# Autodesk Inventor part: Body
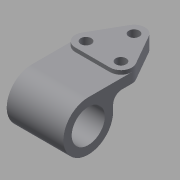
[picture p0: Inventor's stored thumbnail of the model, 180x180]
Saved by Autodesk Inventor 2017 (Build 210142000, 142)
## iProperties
Created: 2010-03
Part Number: Body
Document SubType Name: Modeling
Designer: bhakira
Density: 1 g/cm^3
Material: Generic
Appearance: Default
Author: bhakira
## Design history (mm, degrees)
sketch "Sketch1"
  geometry: L1 (10.853, 41.202)-(30.853, 6.202); L2 (-10.853, 41.202)-(-30.853, 6.202); L3 (-20, -12.5)-(20, -12.5); C1 r 6 at (0, 35); A1 r 12.5 centre (0, 35) between (10.853, 41.202) and (-10.853, 41.202); A2 r 12.5 centre (-20, 0) between (-30.853, 6.202) and (-20, -12.5); A3 r 12.5 centre (20, 0) between (20, -12.5) and (30.853, 6.202); 1 further point
  constraints: 6 end point, 6 point on circle, 6 tangent, 4 centre point, 3 horizontal alignment, 2 equal radius, 1 coincident, 1 vertical alignment, 1 other
  dimensions: "d25" = 35 vertical distance of A1.centre A2.centre; "d27" = 12.5 radius of A1; "d28" = 40 distance of A3.centre A2.centre; "d29" = 20 horizontal distance of A3.centre A1.centre
extrude "Extrusion1" new body sketch "Sketch1" distance "d6" = 16; taper "d7" = 0 deg
workplane "Work Plane2"
workplane "Work Plane3"
sketch "Sketch2"
  geometry: L1 (0, 11.5)-(0, 0); L2 (-12.5, 16)-(6.202, 16) reference; L3 (-50, 11.5)-(0, 11.5); L4 (0, 0)-(-21.5, 0); L5 (-21.5, -17)-(-21.5, 0); L6 (-12.5, 0)-(-12.5, 16) reference; C1 r 19 at (-50, -17); A1 r 28.5 centre (-50, -17) between (-50, 11.5) and (-21.5, -17)
  constraints: 8 end point, 2 centre point, 2 horizontal, 2 point on circle, 2 tangent, 1 coincident, 1 perpendicular, 1 vertical
  dimensions: "d9" = 38 diameter of C1; "d10" = 57 diameter of A1; "d11" = 50 distance from line of L1 C1.centre; "d12" = 33 distance from line of C1.centre L2
extrude "Extrusion2" join sketch "Sketch2" stored distance "d14" = 63.5; taper "d15" = 0 deg
sketch "Sketch3"
  geometry: C1 r 6 at (20, 0) reference; C2 r 6 at (-20, 0) reference; C3 r 6 at (0, 35); 1 further point
  constraints: 1 centre point
extrude "Extrusion3" cut sketch "Sketch3" distance "d16" = 63.5; taper "d17" = 0 deg
node "Sketch4"
hole "Hole1" diameter "d32" = 12; stored, may be unused: countersink angle "d36" = 90 deg, drill point angle "d38" = 118 deg; dims "d33" = 6, "d34" = 4, "d35" = 2082.8, "d37" = 8, "d39" = 10, "d40" = 10
fillet "Fillet1" dims "d42" = 10
body "Solid1"
